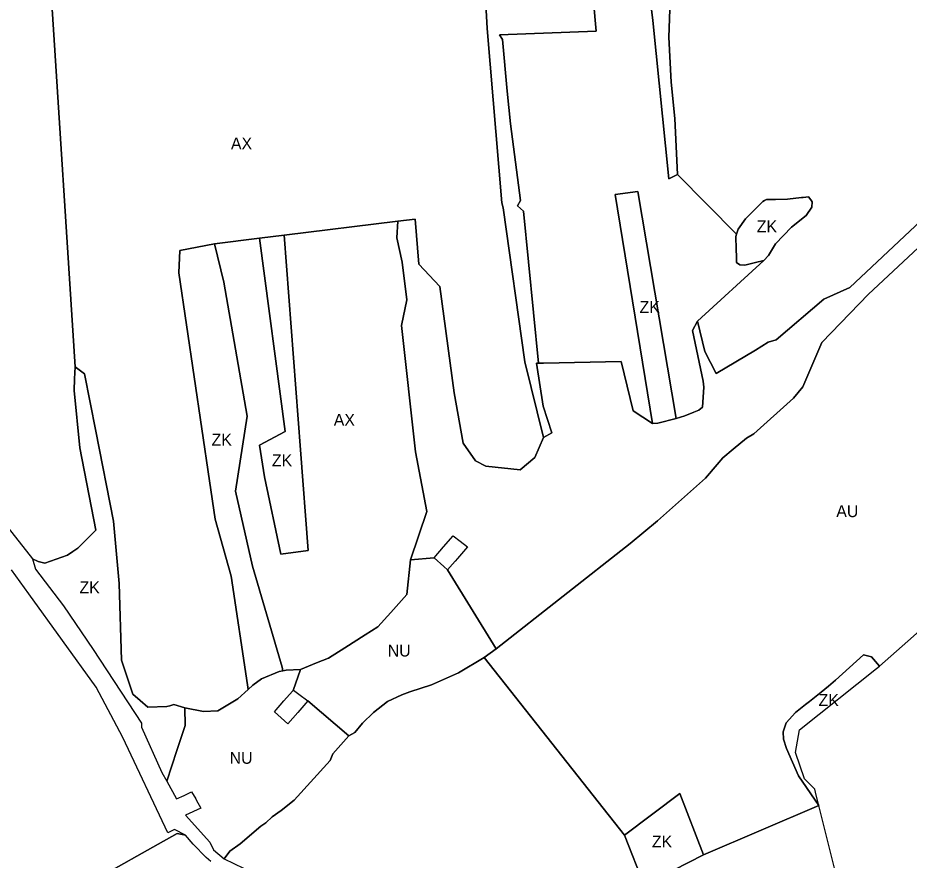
# Model space of a CAD drawing. Extents: x -521939 to -516426, y -1197857 to -1189551.
# Drawn here: x -518826 to -518075, y -1192859 to -1192149 of the extents above; entities that cross this region are included whole.
import ezdxf

# ---------------------------------------------------------------- set-up
doc = ezdxf.new("R2010")
doc.units = 0
for name, color, linetype in [('90710013', 7, 'Continuous'), ('90730013', 7, 'Continuous'), ('90750013', 7, 'Continuous'), ('90760013', 7, 'Continuous')]:
    doc.layers.add(name, color=color, linetype=linetype)

msp = doc.modelspace()

# ---------------------------------------------------------------- linework, layer by layer
at = {"layer": '90710013'}
for points in [[(-518433.03, -1192111.71), (-518430.38, -1192158.5), (-518418.17, -1192305.22), (-518417.11, -1192309.5), (-518398.83, -1192438.94), (-518383.02, -1192502.68), (-518376, -1192498.77), (-518383.26, -1192476.52), (-518388.86, -1192440.23), (-518387.29, -1192440.2)], [(-518387.29, -1192440.2), (-518399.87, -1192312.23), (-518404.85, -1192307.6), (-518402.53, -1192303.29), (-518410.84, -1192238.5), (-518413.57, -1192211.06), (-518417.67, -1192167.63), (-518420.04, -1192163.76), (-518338.7, -1192160.53), (-518343.05, -1192110.36)], [(-518292.25, -1192140.07), (-518291.06, -1192151.72), (-518277.44, -1192285.07), (-518270.3, -1192281.44), (-518272.4, -1192234.03), (-518275.62, -1192203.46), (-518277.55, -1192165.71), (-518276.97, -1192150.12), (-518275.47, -1192109.47)], [(-518291.1, -1192490.96), (-518286.74, -1192490.66), (-518271.35, -1192486.64), (-518303.63, -1192295.61), (-518322.58, -1192298.02), (-518291.1, -1192490.96)], [(-518220.44, -1192331.68), (-518221, -1192333.41), (-518220.75, -1192344.04), (-518220.6, -1192350.58), (-518220.58, -1192355.33), (-518217.73, -1192357.49), (-518213.39, -1192357.63), (-518204.58, -1192355.46), (-518197.49, -1192353.7), (-518193.65, -1192349.45), (-518187.59, -1192339.6), (-518174.06, -1192325.69), (-518161.67, -1192315.75), (-518156.97, -1192308.73), (-518156.84, -1192304.26), (-518157.93, -1192302.77), (-518159.8, -1192300.21), (-518164.28, -1192300.62), (-518165.69, -1192300.79), (-518177.57, -1192302.21), (-518187.59, -1192302.41), (-518195.11, -1192302.31), (-518197.02, -1192303.26), (-518198.41, -1192303.93), (-518212.99, -1192318.52), (-518219.05, -1192327.31), (-518219.89, -1192329.95), (-518220.44, -1192331.68)], [(-518622.32, -1192334.86), (-518600.56, -1192497.7), (-518622.3, -1192509.32), (-518617.91, -1192535.87), (-518604.16, -1192601.03), (-518581.33, -1192597.84), (-518587.71, -1192513.25), (-518601.36, -1192332.27), (-518622.32, -1192334.86)], [(-518631.71, -1192714.98), (-518627.76, -1192711.42), (-518620.49, -1192705.89), (-518605.78, -1192699.67), (-518602.47, -1192699.13), (-518603.15, -1192696.07), (-518628.13, -1192611.12), (-518642.39, -1192548.07), (-518632.61, -1192484.9), (-518652.16, -1192372.1), (-518660.1, -1192339.75), (-518689.29, -1192345.27), (-518690.07, -1192364.15), (-518664.35, -1192539.33), (-518659.64, -1192571.41), (-518646.12, -1192619.46), (-518632.23, -1192710.92), (-518631.71, -1192714.98)], [(-518700.34, -1192792.29), (-518691.82, -1192766.33), (-518684.92, -1192745.27), (-518684.97, -1192730.37), (-518694.24, -1192727.71), (-518697.64, -1192728.85), (-518700.21, -1192729.23), (-518716.38, -1192729.7), (-518722.63, -1192724.36), (-518728.88, -1192719.02), (-518738.44, -1192690.34), (-518740.49, -1192625.81), (-518745.27, -1192573.23), (-518759.95, -1192497.42), (-518769.51, -1192449.11), (-518777.54, -1192443.31), (-518777.99, -1192453.26), (-518778.43, -1192463.21), (-518773.51, -1192511.59), (-518760.07, -1192580.89), (-518775.16, -1192596.03), (-518779.37, -1192598.78), (-518784, -1192601.81), (-518802.87, -1192608.72), (-518808.75, -1192607.14), (-518813.27, -1192604.88), (-518810.91, -1192613.58), (-518787.22, -1192644.65), (-518762.17, -1192681.14), (-518721.68, -1192743.22), (-518721.46, -1192746.65), (-518704.53, -1192784.74), (-518700.34, -1192792.29)], [(-518151.23, -1192812.5), (-518153.39, -1192803.9), (-518154.62, -1192798.99), (-518163.11, -1192790.22), (-518170.83, -1192768.02), (-518167.4, -1192749.03), (-518102.47, -1192697.21), (-518100.15, -1192695.18), (-518106.7, -1192687.4), (-518113.39, -1192685.66), (-518137.16, -1192707.07), (-518143.03, -1192712.13), (-518149.04, -1192717.31), (-518158.94, -1192724.96), (-518162.35, -1192727.6), (-518170.92, -1192734.22), (-518178.69, -1192742.92), (-518181.04, -1192750.48), (-518180.89, -1192756.84), (-518178.51, -1192764.73), (-518168.14, -1192787.68), (-518151.23, -1192812.5)], [(-518314.73, -1192837.73), (-518298.12, -1192879.82), (-518248.32, -1192854.07), (-518268.24, -1192802.56), (-518314.73, -1192837.73)]]:
    msp.add_lwpolyline(points, dxfattribs=at)
at = {"layer": '90730013'}
for points in [[(-518042.12, -1192298.66), (-518125.15, -1192376.45), (-518146.92, -1192386.42), (-518187.13, -1192420.48), (-518193.78, -1192422.38), (-518204.37, -1192429.34), (-518237.7, -1192448.94), (-518242.44, -1192439.65), (-518247.17, -1192430.35), (-518253.27, -1192404.77), (-518257.57, -1192412.61), (-518253.12, -1192433.99), (-518248.67, -1192455.37), (-518247.89, -1192460.32), (-518249.11, -1192477.24), (-518252.12, -1192479.64), (-518256.32, -1192481.37), (-518264.06, -1192484.57), (-518271.35, -1192486.64), (-518286.74, -1192490.66), (-518291.1, -1192490.96), (-518307.39, -1192480.19), (-518317.74, -1192438.8), (-518382.95, -1192440.13), (-518387.29, -1192440.2), (-518388.86, -1192440.23), (-518383.26, -1192476.52), (-518376, -1192498.77), (-518383.02, -1192502.68), (-518390.43, -1192519.48), (-518402.81, -1192529.91), (-518431.68, -1192526.89), (-518440.4, -1192522.41), (-518450.59, -1192507.65), (-518458.28, -1192465.08), (-518470.37, -1192375.68), (-518488.1, -1192356.89), (-518491.21, -1192318.79), (-518505.72, -1192320.55)], [(-518505.72, -1192320.55), (-518506.43, -1192334.55), (-518501.93, -1192355.15), (-518498.06, -1192386.81), (-518502.71, -1192408.4), (-518490.86, -1192514.75), (-518481.29, -1192565.14), (-518494.97, -1192605.71), (-518475.18, -1192604.13), (-518467.14, -1192594.9), (-518459.09, -1192585.66), (-518453.26, -1192590.18), (-518447.16, -1192594.9), (-518455.45, -1192604.56), (-518457.5, -1192606.94), (-518459.66, -1192609.45), (-518463.74, -1192614.21), (-518422.94, -1192680.71), (-518310.17, -1192592.05), (-518287.07, -1192572.91), (-518246.71, -1192536.92), (-518236.78, -1192525.6), (-518232, -1192519.87), (-518223.25, -1192512.63), (-518211.94, -1192503.28), (-518205.79, -1192499.7), (-518172.5, -1192469.71), (-518164.49, -1192459.97), (-518148.58, -1192422.65), (-518109.45, -1192382.02), (-518046.33, -1192323.29)], [(-518581.63, -1192724.62), (-518547.09, -1192753.93), (-518541.9, -1192751.07), (-518535.48, -1192743.39), (-518526.17, -1192734.36), (-518514.28, -1192725.19), (-518502.35, -1192719.43), (-518495.46, -1192716.79), (-518477.39, -1192711.04), (-518454.48, -1192700.99), (-518433.02, -1192688.13), (-518422.94, -1192680.71), (-518463.74, -1192614.21), (-518466.94, -1192611.39), (-518475.18, -1192604.13), (-518494.97, -1192605.71), (-518498.14, -1192635.04), (-518511.48, -1192649.99), (-518522.62, -1192662.28), (-518533.16, -1192668.98), (-518550.33, -1192679.9), (-518564.07, -1192688.66), (-518574.2, -1192692.42), (-518587.61, -1192698.12), (-518593.98, -1192715.86), (-518593.57, -1192715.39), (-518588.95, -1192718.96), (-518581.63, -1192724.62)], [(-518581.63, -1192724.62), (-518589.93, -1192734.28), (-518598.22, -1192743.93), (-518609.66, -1192733.86), (-518601.62, -1192724.63), (-518594.38, -1192716.32), (-518593.98, -1192715.86), (-518587.61, -1192698.12), (-518599.67, -1192698.67), (-518602.47, -1192699.13), (-518605.78, -1192699.67), (-518620.49, -1192705.89), (-518627.76, -1192711.42), (-518631.71, -1192714.98), (-518640.39, -1192722.81), (-518657.43, -1192732.83), (-518669.41, -1192733.38), (-518684.97, -1192730.37), (-518684.92, -1192745.27), (-518691.82, -1192766.33), (-518700.34, -1192792.29), (-518692.09, -1192807.13), (-518685.72, -1192804.11), (-518679.34, -1192801.09), (-518675.94, -1192807.15), (-518675.51, -1192807.93), (-518671.68, -1192814.76), (-518684.56, -1192820.7), (-518663.98, -1192843.4), (-518660.97, -1192849.86), (-518651.89, -1192857.45), (-518647.3, -1192851.1), (-518638.52, -1192844.83), (-518621.09, -1192829.97), (-518616.94, -1192827.29), (-518611.45, -1192822.14), (-518604.02, -1192816.75), (-518592.99, -1192808.25), (-518562.68, -1192774.61), (-518560.44, -1192769.05), (-518547.09, -1192753.93), (-518581.63, -1192724.62)], [(-518663.19, -1192859.9), (-518667.06, -1192856.49), (-518678.07, -1192845.16), (-518684.41, -1192837.53), (-518691.51, -1192836.21), (-518712.04, -1192847.75), (-518787.8, -1192890.35)]]:
    msp.add_lwpolyline(points, dxfattribs=at)
at = {"layer": '90750013'}
for points in [[(-518046.33, -1192323.29), (-518109.45, -1192382.02), (-518148.58, -1192422.65), (-518164.49, -1192459.97), (-518172.5, -1192469.71), (-518205.79, -1192499.7), (-518211.94, -1192503.28), (-518223.25, -1192512.63), (-518232, -1192519.87), (-518236.78, -1192525.6), (-518246.71, -1192536.92), (-518287.07, -1192572.91), (-518310.17, -1192592.05), (-518422.94, -1192680.71), (-518433.02, -1192688.13), (-518314.73, -1192837.73)], [(-518787.8, -1192890.35), (-518712.04, -1192847.75), (-518691.51, -1192836.21), (-518684.41, -1192837.53), (-518693.82, -1192832.93), (-518699.31, -1192835.73), (-518737.24, -1192755.42), (-518759.71, -1192712.86), (-518816.35, -1192634.29), (-518831.07, -1192614.22)], [(-518314.73, -1192837.73), (-518268.24, -1192802.56), (-518248.32, -1192854.07), (-518151.23, -1192812.5), (-518168.14, -1192787.68), (-518178.51, -1192764.73), (-518180.89, -1192756.84), (-518181.04, -1192750.48), (-518178.69, -1192742.92), (-518170.92, -1192734.22), (-518162.35, -1192727.6), (-518158.94, -1192724.96), (-518149.04, -1192717.31), (-518143.03, -1192712.13), (-518137.16, -1192707.07), (-518113.39, -1192685.66), (-518106.7, -1192687.4), (-518100.15, -1192695.18), (-518044.98, -1192646.87)], [(-518314.73, -1192837.73), (-518433.02, -1192688.13), (-518454.48, -1192700.99), (-518477.39, -1192711.04), (-518495.46, -1192716.79), (-518502.35, -1192719.43), (-518514.28, -1192725.19), (-518526.17, -1192734.36), (-518535.48, -1192743.39), (-518541.9, -1192751.07), (-518547.09, -1192753.93), (-518560.44, -1192769.05), (-518562.68, -1192774.61), (-518592.99, -1192808.25), (-518604.02, -1192816.75), (-518611.45, -1192822.14), (-518616.94, -1192827.29), (-518621.09, -1192829.97), (-518638.52, -1192844.83), (-518647.3, -1192851.1), (-518651.89, -1192857.45), (-518619.45, -1192873.36)], [(-518135.12, -1192876.72), (-518151.23, -1192812.5), (-518248.32, -1192854.07), (-518298.12, -1192879.82), (-518314.73, -1192837.73)]]:
    msp.add_lwpolyline(points, dxfattribs=at)
at = {"layer": '90760013'}
for points in [[(-518601.36, -1192332.27), (-518505.72, -1192320.55), (-518491.21, -1192318.79), (-518488.1, -1192356.89), (-518470.37, -1192375.68), (-518458.28, -1192465.08), (-518450.59, -1192507.65), (-518440.4, -1192522.41), (-518431.68, -1192526.89), (-518402.81, -1192529.91), (-518390.43, -1192519.48), (-518383.02, -1192502.68), (-518398.83, -1192438.94), (-518417.11, -1192309.5), (-518418.17, -1192305.22), (-518430.38, -1192158.5), (-518433.03, -1192111.71)], [(-518343.05, -1192110.36), (-518338.7, -1192160.53), (-518420.04, -1192163.76), (-518417.67, -1192167.63), (-518413.57, -1192211.06), (-518410.84, -1192238.5), (-518402.53, -1192303.29), (-518404.85, -1192307.6), (-518399.87, -1192312.23), (-518387.29, -1192440.2)], [(-518275.47, -1192109.47), (-518276.97, -1192150.12), (-518277.55, -1192165.71), (-518275.62, -1192203.46), (-518272.4, -1192234.03), (-518270.3, -1192281.44), (-518220.44, -1192331.68), (-518219.89, -1192329.95), (-518219.05, -1192327.31), (-518212.99, -1192318.52), (-518198.41, -1192303.93), (-518197.02, -1192303.26), (-518195.11, -1192302.31), (-518187.59, -1192302.41), (-518177.57, -1192302.21), (-518165.69, -1192300.79), (-518164.28, -1192300.62), (-518159.8, -1192300.21), (-518157.93, -1192302.77), (-518156.84, -1192304.26), (-518156.97, -1192308.73), (-518161.67, -1192315.75), (-518174.06, -1192325.69), (-518187.59, -1192339.6), (-518193.65, -1192349.45), (-518197.49, -1192353.7), (-518253.27, -1192404.77), (-518247.17, -1192430.35), (-518242.44, -1192439.65), (-518237.7, -1192448.94), (-518204.37, -1192429.34), (-518193.78, -1192422.38), (-518187.13, -1192420.48), (-518146.92, -1192386.42), (-518125.15, -1192376.45), (-518042.12, -1192298.66)], [(-518840.07, -1192570.95), (-518813.27, -1192604.88), (-518808.75, -1192607.14), (-518802.87, -1192608.72), (-518784, -1192601.81), (-518779.37, -1192598.78), (-518775.16, -1192596.03), (-518760.07, -1192580.89), (-518773.51, -1192511.59), (-518778.43, -1192463.21), (-518777.99, -1192453.26), (-518777.54, -1192443.31), (-518797.81, -1192124.2)], [(-518797.81, -1192124.2), (-518777.54, -1192443.31), (-518769.51, -1192449.11), (-518759.95, -1192497.42), (-518745.27, -1192573.23), (-518740.49, -1192625.81), (-518738.44, -1192690.34), (-518728.88, -1192719.02), (-518722.63, -1192724.36), (-518716.38, -1192729.7), (-518700.21, -1192729.23), (-518697.64, -1192728.85), (-518694.24, -1192727.71), (-518684.97, -1192730.37), (-518669.41, -1192733.38), (-518657.43, -1192732.83), (-518640.39, -1192722.81), (-518631.71, -1192714.98), (-518632.23, -1192710.92), (-518646.12, -1192619.46), (-518659.64, -1192571.41), (-518664.35, -1192539.33), (-518690.07, -1192364.15), (-518689.29, -1192345.27), (-518660.1, -1192339.75), (-518622.32, -1192334.86), (-518601.36, -1192332.27)], [(-518387.29, -1192440.2), (-518382.95, -1192440.13), (-518317.74, -1192438.8), (-518307.39, -1192480.19), (-518291.1, -1192490.96), (-518322.58, -1192298.02), (-518303.63, -1192295.61), (-518271.35, -1192486.64), (-518264.06, -1192484.57), (-518256.32, -1192481.37), (-518252.12, -1192479.64), (-518249.11, -1192477.24), (-518247.89, -1192460.32), (-518248.67, -1192455.37), (-518253.12, -1192433.99), (-518257.57, -1192412.61), (-518253.27, -1192404.77), (-518197.49, -1192353.7), (-518204.58, -1192355.46), (-518213.39, -1192357.63), (-518217.73, -1192357.49), (-518220.58, -1192355.33), (-518220.6, -1192350.58), (-518220.75, -1192344.04), (-518221, -1192333.41), (-518220.44, -1192331.68), (-518270.3, -1192281.44), (-518277.44, -1192285.07), (-518291.06, -1192151.72), (-518292.25, -1192140.07)], [(-518622.32, -1192334.86), (-518660.1, -1192339.75), (-518652.16, -1192372.1), (-518632.61, -1192484.9), (-518642.39, -1192548.07), (-518628.13, -1192611.12), (-518603.15, -1192696.07), (-518602.47, -1192699.13), (-518599.67, -1192698.67), (-518587.61, -1192698.12), (-518574.2, -1192692.42), (-518564.07, -1192688.66), (-518550.33, -1192679.9), (-518533.16, -1192668.98), (-518522.62, -1192662.28), (-518511.48, -1192649.99), (-518498.14, -1192635.04), (-518494.97, -1192605.71), (-518481.29, -1192565.14), (-518490.86, -1192514.75), (-518502.71, -1192408.4), (-518498.06, -1192386.81), (-518501.93, -1192355.15), (-518506.43, -1192334.55), (-518505.72, -1192320.55), (-518601.36, -1192332.27), (-518587.71, -1192513.25), (-518581.33, -1192597.84), (-518604.16, -1192601.03), (-518617.91, -1192535.87), (-518622.3, -1192509.32), (-518600.56, -1192497.7), (-518622.32, -1192334.86)]]:
    msp.add_lwpolyline(points, dxfattribs=at)

# ---------------------------------------------------------------- texts
at = {"layer": '90710013'}
for rotation, p in [(360, (-518203.42, -1192329.98)), (0, (-518302.14, -1192397.9)), (0, (-518662.6, -1192509.61)), (0, (-518611.78, -1192527.03)), (0, (-518773.83, -1192633.96)), (0, (-518151.41, -1192728.89)), (360, (-518291.74, -1192847.99))]:
    msp.add_text('ZK', height=10, rotation=rotation, dxfattribs=at).set_placement(p)
at = {"layer": '90730013'}
for p in [(-518514.25, -1192687.19), (-518647.35, -1192777.51)]:
    msp.add_text('NU', height=10, rotation=360, dxfattribs=at).set_placement(p)
at = {"layer": '90750013'}
msp.add_text('AU', height=10, rotation=360, dxfattribs=at).set_placement((-518136.45, -1192569.8))
at = {"layer": '90760013'}
for p in [(-518646.27, -1192260.16), (-518559.66, -1192492.87)]:
    msp.add_text('AX', height=10, rotation=360, dxfattribs=at).set_placement(p)

doc.saveas('drawing.dxf')
